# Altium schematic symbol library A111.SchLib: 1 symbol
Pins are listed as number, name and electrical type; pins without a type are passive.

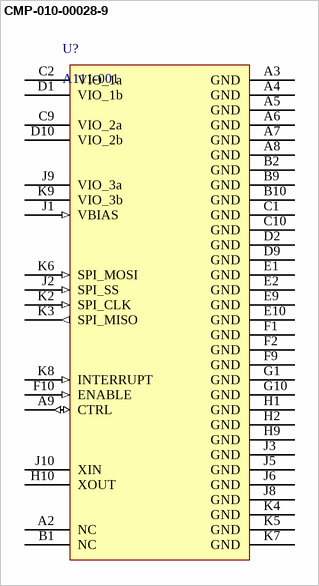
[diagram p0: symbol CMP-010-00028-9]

## CMP-010-00028-9
designator U?, comment A111-001
Acconeer A111-001 pulsed coherent 60 GHz radar sensor; Manufacturer: Acconeer AB; Device revision: R2D
footprint BGA50C50P10X10_520X550X90
pins: A2 NC, A3 GND (power), A4 GND (power), A5 GND (power), A6 GND (power), A7 GND (power), A8 GND (power), A9 CTRL (io), B1 NC, B2 GND (power), B9 GND (power), B10 GND (power), C1 GND (power), C2 VIO_1a (power), C9 VIO_2a (power), C10 GND (power), D1 VIO_1b (power), D2 GND (power), D9 GND (power), D10 VIO_2b (power), E1 GND (power), E2 GND (power), E9 GND (power), E10 GND (power), F1 GND (power), F2 GND (power), F9 GND (power), F10 ENABLE (in), G1 GND (power), G10 GND (power), H1 GND (power), H2 GND (power), H9 GND (power), H10 XOUT, J1 VBIAS (in), J2 SPI_SS (in), J3 GND (power), J5 GND (power), J6 GND (power), J8 GND (power), J9 VIO_3a (power), J10 XIN, K2 SPI_CLK (in), K3 SPI_MISO (out), K4 GND (power), K5 GND (power), K6 SPI_MOSI (in), K7 GND (power), K8 INTERRUPT (in), K9 VIO_3b (power)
